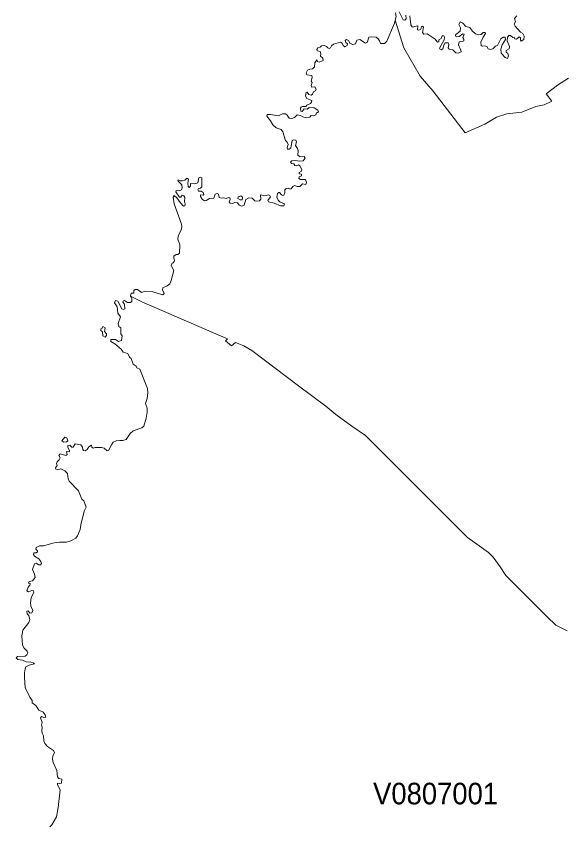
# Model space of a CAD drawing. Extents: x 369010 to 735936, y 6377141 to 6616555.
# Drawn here: x 385899 to 388428, y 6435645 to 6439395 of the extents above; entities that cross this region are included whole.
import ezdxf
from ezdxf.enums import TextEntityAlignment as Align

# ---------------------------------------------------------------- set-up
doc = ezdxf.new("R2010")
doc.units = 0
doc.header["$LTSCALE"] = 40
doc.layers.add('3', color=7, linetype='Continuous', lineweight=13)
doc.layers.add('4', color=7, linetype='Continuous')

msp = doc.modelspace()

# ---------------------------------------------------------------- linework, layer by layer
at = {"layer": '3'}
for points in [[(387657.38, 6439410.21), (387659.53, 6439393.99), (387655.56, 6439376.78)], [(387704.71, 6439399.95), (387706.53, 6439382.24), (387700.57, 6439376.78), (387691.97, 6439377.94), (387674.09, 6439416.17)], [(388001.29, 6439343.35), (387983.42, 6439347.82), (387969.35, 6439363.54), (387957.1, 6439368.67), (387950.98, 6439357.09), (387958.59, 6439341.36), (387956.28, 6439326.14), (387935.59, 6439309.09), (387935.59, 6439302.14), (387941.38, 6439298.83), (387952.8, 6439301.31), (387969.52, 6439313.72), (387975.97, 6439312.07), (387968.86, 6439296.18), (387973.65, 6439288.4), (387974.32, 6439280.95), (387968.19, 6439277.31), (387951.97, 6439276.65), (387948.99, 6439262.58), (387960.75, 6439236.93), (387961.24, 6439230.31), (387949.99, 6439224.02), (387937.08, 6439224.52), (387923.01, 6439239.91), (387906.46, 6439241.56), (387901, 6439248.68), (387904.81, 6439263.91), (387901, 6439272.35), (387888.09, 6439271.19), (387881.47, 6439260.6), (387876.83, 6439244.38), (387869.22, 6439239.41), (387863.76, 6439240.74), (387860.45, 6439246.69), (387882.46, 6439285.26), (387884.94, 6439298.66), (387880.64, 6439303.63), (387872.86, 6439303.46), (387869.06, 6439291.71), (387858.46, 6439285.92), (387857.8, 6439275.66), (387851.51, 6439274.17), (387840.42, 6439288.9), (387803.85, 6439312.73), (387788.29, 6439311.74), (387782, 6439319.35), (387786.3, 6439345), (387781.84, 6439348.98), (387777.04, 6439346.82), (387774.22, 6439335.24), (387765.78, 6439330.94), (387759.82, 6439332.26), (387760.15, 6439350.96), (387745.92, 6439347.32), (387738.8, 6439343.85), (387734, 6439345.17), (387728.54, 6439354.93), (387723.74, 6439397.47)], [(388220.09, 6439396.14), (388208.17, 6439383.9), (388212.97, 6439369.33), (388207.02, 6439357.58), (388211.81, 6439348.31), (388235.98, 6439320.34), (388247.89, 6439314.22), (388253.52, 6439302.47), (388251.7, 6439287.24), (388239.79, 6439278.64), (388236.81, 6439283.77), (388237.14, 6439295.35), (388230.19, 6439299.82), (388217.77, 6439289.06), (388210.82, 6439290.55), (388207.18, 6439298.33), (388200.56, 6439297.01), (388190.46, 6439305.12), (388183.18, 6439305.28), (388176.89, 6439297.67), (388174.25, 6439280.29), (388185.5, 6439253.98), (388183.84, 6439243.88), (388169.94, 6439235.61), (388169.45, 6439227.83), (388178.55, 6439221.7), (388181.69, 6439210.95), (388176.73, 6439199.53), (388166.14, 6439203.5), (388146.77, 6439223.52), (388145.12, 6439242.72), (388152.07, 6439262.58), (388167.13, 6439286.91), (388164.98, 6439297.17), (388156.37, 6439298.66), (388146.11, 6439290.06), (388130.06, 6439258.78), (388120.29, 6439255.8), (388109.86, 6439245.54), (388098.61, 6439240.07), (388087.52, 6439243.38), (388081.07, 6439255.3), (388071.14, 6439257.95), (388058.89, 6439255.63), (388053.59, 6439259.93), (388053.43, 6439275.16), (388063.03, 6439297.17), (388074.94, 6439314.88), (388072.46, 6439319.68), (388063.52, 6439318.85), (388054.42, 6439310.08), (388040.35, 6439308.59), (388027.44, 6439313.72), (388012.55, 6439326.8), (388001.29, 6439343.35)], [(387655.56, 6439376.78), (387652.41, 6439362.38), (387617.66, 6439278.97), (387605.57, 6439268.71), (387587.37, 6439268.54), (387583.73, 6439280.62), (387576.94, 6439290.72), (387566.85, 6439298.33), (387545.33, 6439299.82), (387534.08, 6439297.17), (387530.1, 6439288.73), (387527.62, 6439274), (387517.36, 6439270.86), (387492.37, 6439287.08), (387477.8, 6439283.6), (387471.35, 6439266.39), (387459.1, 6439263.41), (387447.35, 6439268.04), (387438.58, 6439282.61), (387429.48, 6439287.57), (387423.68, 6439282.61), (387427.16, 6439273.84), (387434.28, 6439267.38), (387433.78, 6439258.94), (387423.02, 6439253.15), (387413.92, 6439259.44), (387410.11, 6439270.86), (387401.84, 6439274.17), (387370.06, 6439265.89), (387360.13, 6439258.28), (387356.16, 6439248.51), (387349.87, 6439245.54), (387343.08, 6439248.18), (387337.95, 6439255.3), (387328.02, 6439259.27), (387313.62, 6439258.44), (387307.83, 6439250.83), (387296.91, 6439248.18), (387292.11, 6439241.07), (387294.26, 6439234.78), (387307.83, 6439231.8), (387311.31, 6439220.54), (387309.98, 6439209.46), (387320.74, 6439201.18), (387321.73, 6439190.42), (387304.03, 6439181.98), (387295.92, 6439185.46), (387292.11, 6439192.08), (387283.5, 6439179.17), (387281.85, 6439160.3), (387273.08, 6439151.53), (387260.33, 6439149.71), (387249.08, 6439144.25), (387242.46, 6439131.83), (387245.6, 6439123.06), (387269.77, 6439120.58), (387270.59, 6439111.48), (387265.46, 6439094.6), (387270.1, 6439088.14), (387265.46, 6439073.08), (387268.44, 6439065.63), (387283.83, 6439067.62), (387289.96, 6439056.36), (387286.81, 6439048.75), (387277.54, 6439044.94), (387273.08, 6439033.03), (387265.46, 6439028.23), (387254.71, 6439032.04), (387248.25, 6439042.46), (387243.45, 6439041.14), (387239.64, 6439025.08), (387245.77, 6439013.17), (387268.94, 6439003.9), (387268.44, 6438996.45), (387263.64, 6438990.66), (387246.76, 6438983.05), (387240.8, 6438976.59), (387225.25, 6438976.76), (387219.12, 6438973.94), (387216.97, 6438967.99), (387218.29, 6438954.08), (387223.76, 6438953.92), (387233.19, 6438966.33), (387246.93, 6438963.35), (387256.53, 6438971.79), (387280.36, 6438969.81), (387297.57, 6438959.38), (387300.22, 6438953.92), (387296.74, 6438948.12), (387290.79, 6438946.97), (387287.81, 6438938.36), (387277.54, 6438933.89), (387266.62, 6438934.22), (387259.34, 6438926.94), (387243.45, 6438923.8), (387228.06, 6438928.26), (387216.14, 6438934.22), (387201.91, 6438937.7), (387188.5, 6438924.79), (387176.09, 6438920.49)], [(388242.43, 6438950.44), (388173.09, 6438943.16), (388124.76, 6438927.6), (388071.8, 6438894.67), (387980.44, 6438854.45), (387832.48, 6439048.25), (387772.24, 6439117.77), (387696.44, 6439248.51), (387655.56, 6439376.78)], [(387655.56, 6439376.78), (387696.44, 6439248.51), (387772.24, 6439117.77), (387832.48, 6439048.25), (387980.44, 6438854.45), (388071.8, 6438894.67), (388124.76, 6438927.6), (388173.09, 6438943.16), (388242.43, 6438950.44), (388308.14, 6438976.1), (388346.54, 6438983.38), (388381.29, 6439001.58), (388355.64, 6439034.52), (388408.6, 6439074.74), (388459.74, 6439107.67)], [(388459.74, 6439107.67), (388408.6, 6439074.74), (388355.64, 6439034.52), (388381.29, 6439001.58), (388346.54, 6438983.38), (388308.14, 6438976.1), (388242.43, 6438950.44)], [(387176.09, 6438920.49), (387164.67, 6438921.64), (387155.07, 6438936.37), (387147.13, 6438942.17), (387133.06, 6438942.17), (387114.03, 6438933.4), (387077.12, 6438940.02), (387062.89, 6438939.02), (387060.24, 6438932.07), (387077.95, 6438909.23), (387087.88, 6438891.03), (387103.43, 6438876.79), (387126.94, 6438870.01), (387135.05, 6438859.08), (387146.96, 6438818.37), (387155.24, 6438811.42), (387159.38, 6438800.5), (387154.41, 6438786.59), (387157.06, 6438778.48), (387164.34, 6438777.99), (387171.62, 6438784.44), (387178.41, 6438818.87), (387184.2, 6438821.68), (387194.46, 6438821.02), (387198.76, 6438813.07), (387193.8, 6438796.19), (387203.56, 6438781.79), (387206.38, 6438771.53), (387205.05, 6438750.02), (387215.32, 6438742.24), (387234.18, 6438743.89), (387238.49, 6438736.45), (387229.05, 6438724.53), (387210.02, 6438722.21), (387194.46, 6438725.69), (387176.75, 6438724.53), (387170.79, 6438718.74), (387175.43, 6438711.79), (387186.19, 6438710.46), (387189.99, 6438703.18), (387196.61, 6438701.52), (387207.21, 6438706.65), (387213.83, 6438701.03), (387223.59, 6438684.31), (387221.94, 6438677.19), (387211.01, 6438671.07), (387210.18, 6438664.78), (387220.94, 6438662.13), (387221.94, 6438654.69), (387211.01, 6438649.56), (387209.36, 6438642.6), (387216.64, 6438637.8), (387240.14, 6438637.31), (387244.94, 6438623.41), (387240.97, 6438614.63), (387226.07, 6438617.45), (387213.16, 6438605.04), (387201.91, 6438604.87), (387189.99, 6438610.17), (387181.88, 6438606.19), (387173.61, 6438595.1), (387165.33, 6438595.27), (387159.87, 6438598.42), (387149.78, 6438595.44), (387144.31, 6438589.31), (387144.31, 6438576.24), (387139.02, 6438565.48), (387134.05, 6438563.99), (387128.09, 6438566.64), (387119.65, 6438576.9), (387115.68, 6438577.89), (387110.39, 6438573.26), (387107.24, 6438555.55), (387112.54, 6438541.98), (387121.64, 6438533.87), (387142.33, 6438525.59), (387140.01, 6438515.66), (387123.46, 6438515.33), (387094.33, 6438527.91), (387068.18, 6438533.87), (387065.2, 6438539.83), (387077.45, 6438557.37), (387075.3, 6438564.16), (387067.85, 6438567.3), (387052.13, 6438562.83), (387031.11, 6438567.13), (387032.1, 6438547.11), (387026.31, 6438539.66), (387014.56, 6438537.01), (387004.63, 6438539.66), (386992.71, 6438551.41), (386976.82, 6438552.74), (386963.09, 6438545.12), (386955.64, 6438519.47), (386945.38, 6438513.84), (386932.63, 6438518.15), (386924.52, 6438529.9), (386911.95, 6438531.55), (386902.18, 6438527.25), (386890.93, 6438527.74)], [(386890.93, 6438527.74), (386885.63, 6438534.53), (386890.1, 6438544.46), (386889.77, 6438552.24), (386882.49, 6438554.23), (386872.56, 6438549.09), (386859.32, 6438553.23), (386850.21, 6438550.92), (386839.12, 6438554.89), (386837.14, 6438570.44), (386829.69, 6438573.59), (386820.42, 6438569.45), (386815.46, 6438550.92), (386794.44, 6438550.09), (386779.54, 6438540.16), (386771.76, 6438539.16), (386760.68, 6438547.44), (386752.57, 6438558.69), (386753.72, 6438567.13), (386765.64, 6438564.49), (386769.12, 6438568.96), (386765.31, 6438577.56), (386756.7, 6438583.52), (386743.79, 6438584.35), (386741.15, 6438589.48), (386744.46, 6438596.26), (386753.06, 6438597.59), (386758.86, 6438604.04), (386758.86, 6438645.75), (386751.08, 6438648.56), (386745.45, 6438645.42), (386740.15, 6438622.91), (386727.24, 6438618.28), (386707.38, 6438618.94), (386706.06, 6438606.69), (386700.93, 6438601.56), (386695.3, 6438605.37), (386694.31, 6438620.59), (386697.12, 6438639.46), (386690.01, 6438643.76), (386681.23, 6438634.49), (386670.15, 6438631.02), (386658.89, 6438632.01), (386650.12, 6438636.15), (386648.13, 6438631.02), (386665.84, 6438612.98), (386668.32, 6438599.57), (386664.85, 6438589.97), (386654.42, 6438584.68), (386639.69, 6438586.66), (386638.37, 6438580.71), (386656.41, 6438555.55), (386661.87, 6438555.38), (386668.32, 6438565.15), (386675.94, 6438562), (386681.23, 6438553.89), (386678.75, 6438536.02), (386682.56, 6438523.61), (386680.41, 6438515.17), (386674.94, 6438514.84), (386658.56, 6438531.88), (386643.66, 6438553.23), (386631.42, 6438563.33), (386626.29, 6438556.54), (386630.59, 6438524.6), (386665.35, 6438431.42), (386666.17, 6438419.01), (386663.19, 6438405.11), (386648.96, 6438375.48), (386647.47, 6438361.91), (386657.73, 6438335.1), (386655.58, 6438296.87), (386647.97, 6438289.92), (386640.35, 6438289.92), (386629.6, 6438282.8), (386629.1, 6438272.7), (386632.74, 6438264.59), (386631.42, 6438257.48), (386626.95, 6438252.02), (386621.82, 6438249.53), (386617.85, 6438239.77), (386629.6, 6438216.1), (386616.69, 6438169.76), (386610.23, 6438153.87), (386599.14, 6438144.44), (386578.62, 6438135.67), (386577.3, 6438126.56), (386585.41, 6438109.85), (386578.62, 6438103.06), (386531.62, 6438117.29), (386497.19, 6438119.45), (386479.98, 6438113.49), (386461.44, 6438127.23), (386449.86, 6438128.55), (386443.9, 6438122.43), (386443.74, 6438110.34), (386431.49, 6438110.34), (386428.84, 6438096.44), (386481.14, 6438071.12), (386802.22, 6437932.26)], [(386428.84, 6438096.44), (386430, 6438094.79), (386434.63, 6438084.69), (386434.8, 6438072.77), (386428.01, 6438067.31), (386414.28, 6438067.15), (386400.7, 6438076.58), (386394.91, 6438074.43), (386393.09, 6438068.47), (386400.21, 6438060.2), (386402.69, 6438038.35), (386394.58, 6438034.38), (386388.13, 6438037.52), (386369.92, 6438074.43), (386359.16, 6438076.58), (386354.86, 6438066.65), (386366.11, 6438047.95), (386370.09, 6438018.16), (386382.33, 6438000.95), (386371.41, 6437969.83), (386374.89, 6437956.26), (386383.33, 6437949.47), (386383.82, 6437922.83), (386389.28, 6437913.23), (386386.31, 6437891.88), (386373.23, 6437886.25), (386359.16, 6437896.51), (386337.48, 6437895.85), (386337.48, 6437887.41), (386355.36, 6437876.49), (386385.64, 6437850.83), (386394.25, 6437837.92), (386416.43, 6437831.8), (386423.88, 6437814.09), (386431.98, 6437808.13), (386441.42, 6437782.31), (386454.66, 6437772.55), (386458.47, 6437765.27), (386472.37, 6437757.99), (386507.79, 6437668.12), (386509.44, 6437648.59), (386505.63, 6437621.78), (386498.02, 6437598.77), (386505.3, 6437578.25), (386505.8, 6437559.22), (386501.5, 6437531.25), (386489.91, 6437494.17), (386480.81, 6437485.9), (386440.43, 6437472.99), (386427.02, 6437460.58), (386408.32, 6437431.78), (386392.43, 6437427.31), (386378.53, 6437428.3), (386361.48, 6437426.81), (386348.41, 6437420.19), (386339.8, 6437408.11), (386326.89, 6437381.46), (386319.77, 6437379.81), (386305.87, 6437392.72), (386294.45, 6437395.7), (386264.99, 6437395.7), (386255.56, 6437391.73), (386249.77, 6437396.19), (386247.78, 6437405.3), (386235.86, 6437398.68), (386227.59, 6437385.44), (386218.15, 6437379.97), (386211.04, 6437381.13), (386207.56, 6437386.59), (386206.73, 6437396.69), (386198.46, 6437407.61), (386172.81, 6437412.25), (386163.54, 6437396.52), (386156.75, 6437396.86), (386146.99, 6437405.79), (386137.72, 6437405.13), (386138.71, 6437394.54), (386146.33, 6437381.46), (386145.83, 6437375.51), (386131.26, 6437375.84), (386134.57, 6437363.09), (386129.11, 6437358.46), (386102.3, 6437365.41), (386096.18, 6437357.3), (386102.3, 6437347.7), (386097.83, 6437337.77), (386088.07, 6437329.16), (386085.42, 6437320.23), (386089.23, 6437311.95), (386080.95, 6437301.19), (386082.61, 6437294.24), (386090.22, 6437291.6), (386105.28, 6437295.57), (386124.15, 6437287.46), (386137.06, 6437274.38), (386139.7, 6437250.05), (386144.01, 6437239.46), (386187.37, 6437194.61), (386202.93, 6437156.05), (386212.53, 6437147.28)], [(388453.45, 6436544.68), (388399.99, 6436570.83), (388359.44, 6436611.04), (388240.94, 6436729.05), (388168.78, 6436800.88), (388142.47, 6436841.42), (388109.7, 6436886.11), (388089.01, 6436907.63), (387990.7, 6436978.13), (387800.37, 6437167.47), (387517.36, 6437450.15), (387455.46, 6437494.01), (387380.82, 6437548.79), (387333.49, 6437586.52), (387208.03, 6437680.53), (386991.72, 6437844.38), (386953.82, 6437867.05), (386922.37, 6437878.8), (386914.76, 6437881.78), (386897.55, 6437866.56), (386869.58, 6437890.39), (386877.52, 6437899.49), (386802.22, 6437932.26), (386481.14, 6438071.12), (386428.84, 6438096.44)], [(386802.22, 6437932.26), (386877.52, 6437899.49), (386869.58, 6437890.39), (386897.55, 6437866.56), (386914.76, 6437881.78), (386922.37, 6437878.8), (386953.82, 6437867.05), (386991.72, 6437844.38), (387208.03, 6437680.53), (387333.49, 6437586.52), (387380.82, 6437548.79), (387455.46, 6437494.01), (387517.36, 6437450.15), (387800.37, 6437167.47), (387990.7, 6436978.13), (388089.01, 6436907.63), (388109.7, 6436886.11), (388142.47, 6436841.42), (388168.78, 6436800.88), (388240.94, 6436729.05), (388359.44, 6436611.04), (388399.99, 6436570.83), (388453.45, 6436544.68)], [(386212.53, 6437147.28), (386223.78, 6437118.64), (386213.19, 6437100.6), (386197.96, 6437036.72), (386194.98, 6437014.38), (386183.07, 6436985.74), (386174.96, 6436975.32), (386152.12, 6436961.58), (386131.93, 6436956.62), (386099.98, 6436956.62), (386075.32, 6436953.47), (386025.01, 6436939.9), (386006.97, 6436938.91), (385990.59, 6436930.96), (385988.93, 6436923.35), (385997.7, 6436916.4), (385998.03, 6436911.27), (385990.75, 6436907.13), (385980.49, 6436906.63), (385979.5, 6436898.52), (385984.13, 6436890.91), (386003, 6436878.5), (386012.27, 6436867.24), (386016.07, 6436857.97), (386011.27, 6436851.02), (386003.5, 6436851.19), (385991.08, 6436858.14), (385982.97, 6436855.49), (385974.53, 6436829.01), (385983.8, 6436807.83), (385986.78, 6436791.94), (385974.86, 6436776.71), (385958.97, 6436773.07), (385955.66, 6436766.45), (385964.6, 6436763.47), (385962.62, 6436756.19), (385954.01, 6436747.75), (385948.71, 6436730.54), (385955.5, 6436725.57), (385971.22, 6436731.53), (385978.34, 6436730.37), (385980.49, 6436724.58), (385968.41, 6436697.6), (385965.43, 6436675.59), (385966.92, 6436659.37), (385975.52, 6436638.85), (385971.39, 6436628.26), (385962.12, 6436626.93), (385953.84, 6436637.69), (385948.71, 6436636.03), (385949.54, 6436623.95), (385957.15, 6436615.51), (385962.12, 6436596.31), (385956.66, 6436583.24), (385929.18, 6436547.99), (385925.54, 6436522.17), (385927.69, 6436477.81), (385935.31, 6436464.74), (385949.04, 6436451), (385951.86, 6436443.39), (385948.05, 6436432.96), (385940.11, 6436427.66), (385904.03, 6436425.68), (385898.57, 6436419.55), (385906.18, 6436412.6), (385927.69, 6436408.96), (385945.24, 6436400.85), (385966.75, 6436400.36), (385977.84, 6436396.88), (385982.97, 6436391.58), (385958.31, 6436385.13), (385943.75, 6436377.52), (385939.61, 6436368.58), (385937.29, 6436350.54), (385936.8, 6436330.35), (385940.93, 6436282.35), (385961.13, 6436237), (385972.21, 6436221.45), (385972.21, 6436210.36), (385989.1, 6436198.94), (386004.16, 6436176.43), (386023.02, 6436168.32), (386032.62, 6436155.25), (386036.26, 6436143.99), (386026.67, 6436143.33), (386016.07, 6436148.13), (386012.1, 6436141.34), (386019.22, 6436119.17), (386015.25, 6436107.91), (386019.71, 6436098.81), (386017.4, 6436080.93), (386019.22, 6436070.51), (386025.51, 6436057.6), (386026.83, 6436034.59), (386031.13, 6436022.01), (386044.04, 6436008.77), (386072.34, 6435989.91), (386076.65, 6435979.81), (386068.7, 6435964.58), (386066.22, 6435949.36)], [(386066.22, 6435949.36), (386070.19, 6435934.3), (386086.91, 6435897.72), (386089.72, 6435868.1), (386095.85, 6435859.49), (386109.75, 6435857.17), (386109.25, 6435838.97), (386099.82, 6435836.32), (386090.38, 6435838.64), (386089.39, 6435830.86), (386103.13, 6435807.36), (386093.69, 6435726.09), (386086.08, 6435681.9), (386064.4, 6435645.82), (386054.3, 6435635.4)]]:
    msp.add_lwpolyline(points, dxfattribs=at)
for points in [[(386946.04, 6438544.13), (386947.7, 6438555.88), (386940.25, 6438562.83), (386927.83, 6438557.04), (386926.68, 6438549.26), (386937.27, 6438543.63)], [(386310.84, 6437907.44), (386316.63, 6437913.89), (386317.13, 6437922.83), (386307.53, 6437932.76), (386311.66, 6437950.3), (386301.07, 6437956.92), (386297.76, 6437949.14), (386291.31, 6437944.84), (386291.31, 6437937.39), (386298.42, 6437930.94), (386299.91, 6437913.23)], [(386124.81, 6437442.87), (386110.58, 6437425.82), (386118.85, 6437420.36), (386131.93, 6437421.85), (386137.55, 6437426.81), (386133.25, 6437439.23)]]:
    msp.add_lwpolyline(points, close=True, dxfattribs=at)

# ---------------------------------------------------------------- texts
at = {"layer": '4', "width": 0.95}
msp.add_text('V0807001', height=100, dxfattribs=at).set_placement((387842.92, 6435740.38), align=Align.CENTER)

doc.saveas('drawing.dxf')
